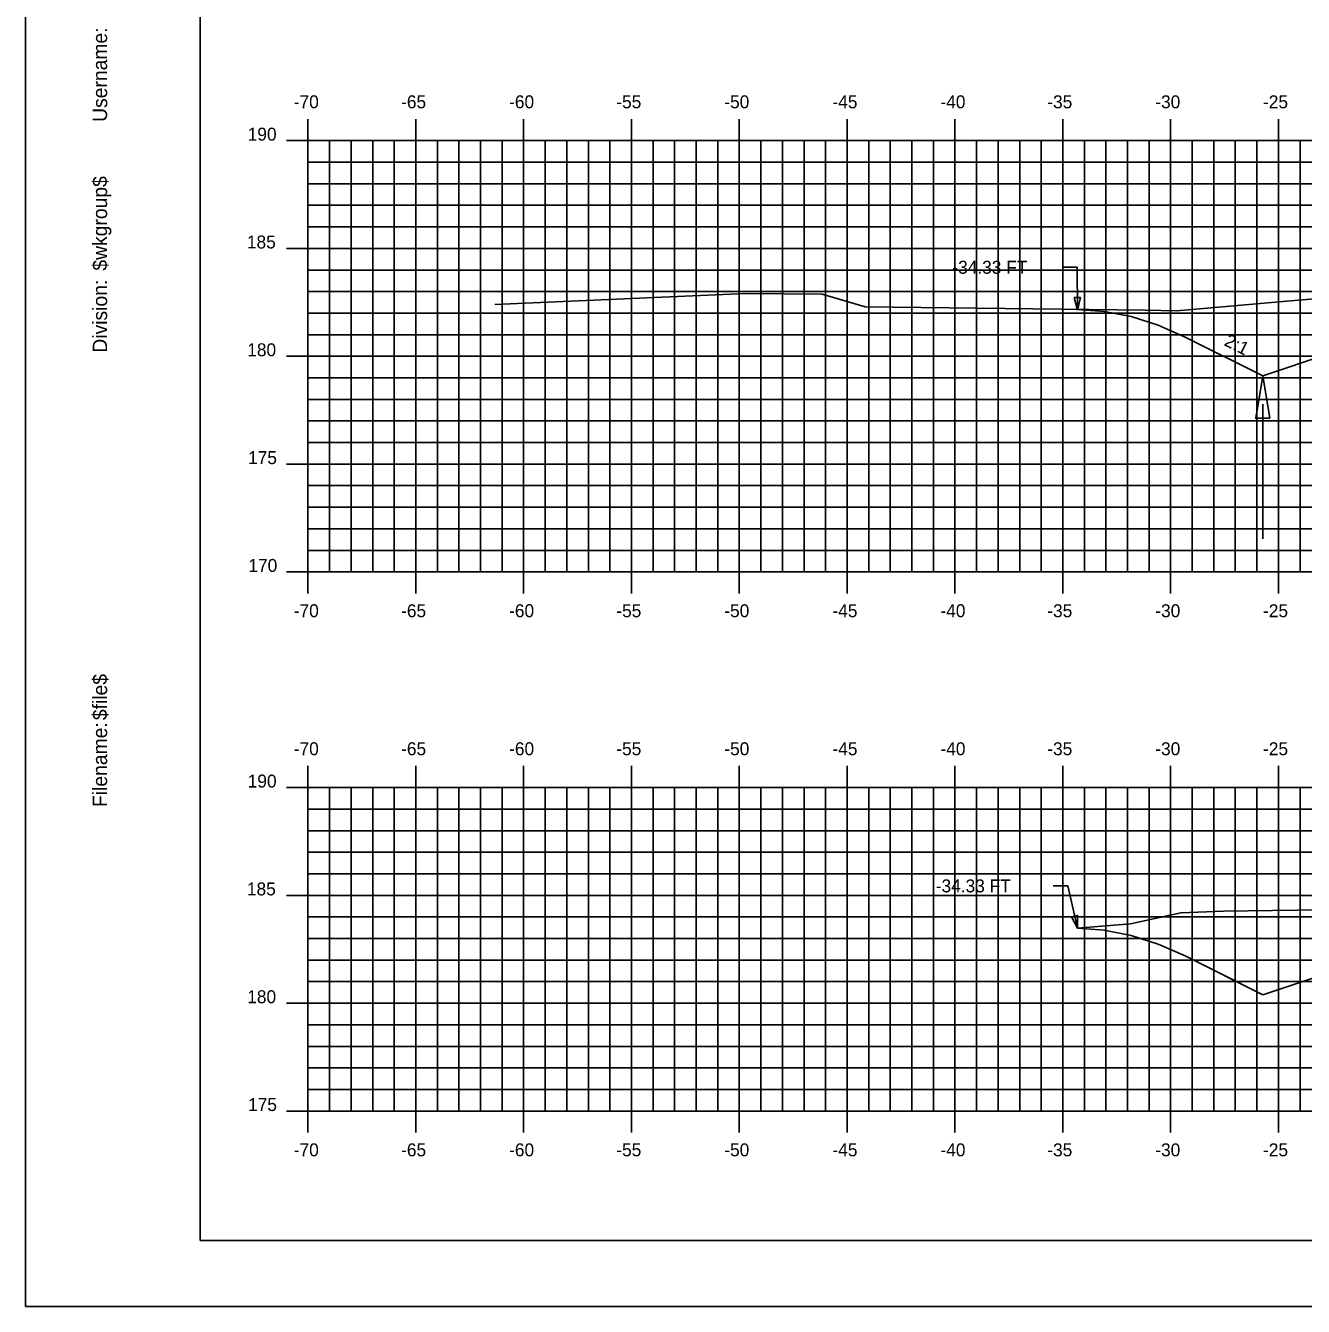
# Model space of a CAD drawing. Extents: x 1139872 to 1140042, y 608981 to 609091.
# Drawn here: x 1139871.9 to 1139931.1, y 608981.3 to 609040.7 of the extents above; entities that cross this region are included whole.
import ezdxf

# ---------------------------------------------------------------- set-up
doc = ezdxf.new("R2010")
doc.units = 0
for name, color, linetype in [('ANNOTATION', 7, 'Continuous'), ('BORDER', 7, 'Continuous'), ('D_Drainage_Ditch_Line', 7, 'Continuous'), ('D_Roadway_SlopeLines', 7, 'Continuous'), ('D_Text_Standard', 7, 'Continuous'), ('H_V ANNOTATION', 7, 'Continuous'), ('MAJOR', 7, 'Continuous'), ('MINOR', 7, 'Continuous'), ('PLOT BOUNDARY', 7, 'Continuous'), ('S_Roadway_Centerline', 7, 'Continuous')]:
    doc.layers.add(name, color=color, linetype=linetype)

msp = doc.modelspace()

# ---------------------------------------------------------------- linework, layer by layer
msp.add_lwpolyline([(1139920.649, 609027.509), (1139921.899, 609027.417), (1139923.149, 609027.173), (1139924.399, 609026.776), (1139925.649, 609026.227), (1139929.25, 609024.427), (1139932.25, 609025.427), (1139939.974, 609028.001), (1139939.975, 609028.001), (1139943.975, 609028.161), (1139954.975, 609028.381), (1139965.975, 609028.161), (1139969.975, 609028.001), (1139977.698, 609025.427), (1139980.698, 609024.427), (1139983.25, 609025.703), (1139984.5, 609026.247), (1139985.75, 609026.628), (1139987, 609026.848), (1139988.25, 609026.905)])
at = {"layer": 'BORDER'}
msp.add_lwpolyline([(1139879.975, 608984.335), (1140039.975, 608984.335), (1140039.975, 609089.335), (1139879.975, 609089.335)], close=True, dxfattribs=at)
at = {"layer": 'D_Drainage_Ditch_Line'}
msp.add_line((1139929.25, 609023.115), (1139929.25, 609016.871), dxfattribs=at)
msp.add_lwpolyline([(1139929.578, 609022.458), (1139928.922, 609022.458), (1139929.25, 609024.427)], close=True, dxfattribs=at)
at = {"layer": 'D_Roadway_SlopeLines'}
msp.add_line((1139929.25, 608995.726), (1139927.25, 608996.726), dxfattribs=at)
for points in [[(1139929.25, 609024.427), (1139925.649, 609026.227), (1139924.399, 609026.776), (1139923.149, 609027.173), (1139921.899, 609027.417), (1139920.649, 609027.509)], [(1139932.25, 609025.427), (1139929.25, 609024.427)], [(1139939.975, 608999.301), (1139929.25, 608995.726)], [(1139929.25, 608995.726), (1139925.649, 608997.527), (1139924.399, 608998.075), (1139923.149, 608998.472), (1139921.899, 608998.716), (1139920.649, 608998.808)]]:
    msp.add_lwpolyline(points, dxfattribs=at)
at = {"layer": 'D_Text_Standard'}
for points in [[(1139920.649, 609027.477), (1139920.645, 609029.461), (1139919.965, 609029.461)], [(1139920.649, 608998.808), (1139920.209, 609000.775), (1139919.529, 609000.775)]]:
    msp.add_lwpolyline(points, dxfattribs=at)
for points in [[(1139920.649, 609027.477), (1139920.502, 609028.059), (1139920.794, 609028.06)], [(1139920.649, 608998.808), (1139920.38, 608999.345), (1139920.664, 608999.408)]]:
    msp.add_lwpolyline(points, close=True, dxfattribs=at)
at = {"layer": 'MAJOR'}
for p, q in [((1139884.975, 609036.337), (1139884.975, 609035.335)), ((1139889.975, 609036.337), (1139889.975, 609035.335)), ((1139894.975, 609036.337), (1139894.975, 609035.335)), ((1139899.975, 609036.337), (1139899.975, 609035.335)), ((1139904.975, 609036.337), (1139904.975, 609035.335)), ((1139909.975, 609036.337), (1139909.975, 609035.335)), ((1139914.975, 609036.337), (1139914.975, 609035.335)), ((1139919.975, 609036.337), (1139919.975, 609035.335)), ((1139924.975, 609036.337), (1139924.975, 609035.335)), ((1139929.975, 609036.337), (1139929.975, 609035.335)), ((1139883.973, 609035.335), (1139884.975, 609035.335)), ((1139884.975, 609035.335), (1140024.975, 609035.335)), ((1139884.975, 609015.335), (1139884.975, 609035.335)), ((1139884.975, 609015.335), (1139884.975, 609035.335)), ((1139884.975, 609035.335), (1140024.975, 609035.335)), ((1139889.975, 609015.335), (1139889.975, 609035.335)), ((1139894.975, 609015.335), (1139894.975, 609035.335)), ((1139899.975, 609015.335), (1139899.975, 609035.335)), ((1139904.975, 609015.335), (1139904.975, 609035.335)), ((1139909.975, 609015.335), (1139909.975, 609035.335)), ((1139914.975, 609015.335), (1139914.975, 609035.335)), ((1139919.975, 609015.335), (1139919.975, 609035.335)), ((1139924.975, 609015.335), (1139924.975, 609035.335)), ((1139929.975, 609015.335), (1139929.975, 609035.335)), ((1139883.973, 609030.335), (1139884.975, 609030.335)), ((1139884.975, 609030.335), (1140024.975, 609030.335)), ((1139883.973, 609025.335), (1139884.975, 609025.335)), ((1139884.975, 609025.335), (1140024.975, 609025.335)), ((1139883.973, 609020.335), (1139884.975, 609020.335)), ((1139884.975, 609020.335), (1140024.975, 609020.335)), ((1139883.973, 609015.335), (1139884.975, 609015.335)), ((1139884.975, 609015.335), (1140024.975, 609015.335)), ((1139884.975, 609015.335), (1140024.975, 609015.335)), ((1139884.975, 609014.333), (1139884.975, 609015.335)), ((1139889.975, 609014.333), (1139889.975, 609015.335)), ((1139894.975, 609014.333), (1139894.975, 609015.335)), ((1139899.975, 609014.333), (1139899.975, 609015.335)), ((1139904.975, 609014.333), (1139904.975, 609015.335)), ((1139909.975, 609014.333), (1139909.975, 609015.335)), ((1139914.975, 609014.333), (1139914.975, 609015.335)), ((1139919.975, 609014.333), (1139919.975, 609015.335)), ((1139924.975, 609014.333), (1139924.975, 609015.335)), ((1139929.975, 609014.333), (1139929.975, 609015.335)), ((1139884.975, 609006.337), (1139884.975, 609005.335)), ((1139889.975, 609006.337), (1139889.975, 609005.335)), ((1139894.975, 609006.337), (1139894.975, 609005.335)), ((1139899.975, 609006.337), (1139899.975, 609005.335)), ((1139904.975, 609006.337), (1139904.975, 609005.335)), ((1139909.975, 609006.337), (1139909.975, 609005.335)), ((1139914.975, 609006.337), (1139914.975, 609005.335)), ((1139919.975, 609006.337), (1139919.975, 609005.335)), ((1139924.975, 609006.337), (1139924.975, 609005.335)), ((1139929.975, 609006.337), (1139929.975, 609005.335)), ((1139883.973, 609005.335), (1139884.975, 609005.335)), ((1139884.975, 609005.335), (1140024.975, 609005.335)), ((1139884.975, 608990.335), (1139884.975, 609005.335)), ((1139884.975, 608990.335), (1139884.975, 609005.335)), ((1139884.975, 609005.335), (1140024.975, 609005.335)), ((1139889.975, 608990.335), (1139889.975, 609005.335)), ((1139894.975, 608990.335), (1139894.975, 609005.335)), ((1139899.975, 608990.335), (1139899.975, 609005.335)), ((1139904.975, 608990.335), (1139904.975, 609005.335)), ((1139909.975, 608990.335), (1139909.975, 609005.335)), ((1139914.975, 608990.335), (1139914.975, 609005.335)), ((1139919.975, 608990.335), (1139919.975, 609005.335)), ((1139924.975, 608990.335), (1139924.975, 609005.335)), ((1139929.975, 608990.335), (1139929.975, 609005.335)), ((1139883.973, 609000.335), (1139884.975, 609000.335)), ((1139884.975, 609000.335), (1140024.975, 609000.335)), ((1139883.973, 608995.335), (1139884.975, 608995.335)), ((1139884.975, 608995.335), (1140024.975, 608995.335)), ((1139883.973, 608990.335), (1139884.975, 608990.335)), ((1139884.975, 608990.335), (1140024.975, 608990.335)), ((1139884.975, 608990.335), (1140024.975, 608990.335)), ((1139884.975, 608989.333), (1139884.975, 608990.335)), ((1139889.975, 608989.333), (1139889.975, 608990.335)), ((1139894.975, 608989.333), (1139894.975, 608990.335)), ((1139899.975, 608989.333), (1139899.975, 608990.335)), ((1139904.975, 608989.333), (1139904.975, 608990.335)), ((1139909.975, 608989.333), (1139909.975, 608990.335)), ((1139914.975, 608989.333), (1139914.975, 608990.335)), ((1139919.975, 608989.333), (1139919.975, 608990.335)), ((1139924.975, 608989.333), (1139924.975, 608990.335)), ((1139929.975, 608989.333), (1139929.975, 608990.335))]:
    msp.add_line(p, q, dxfattribs=at)
at = {"layer": 'MINOR'}
for p, q in [((1139885.975, 609015.335), (1139885.975, 609035.335)), ((1139886.975, 609015.335), (1139886.975, 609035.335)), ((1139887.975, 609015.335), (1139887.975, 609035.335)), ((1139888.975, 609015.335), (1139888.975, 609035.335)), ((1139890.975, 609015.335), (1139890.975, 609035.335)), ((1139891.975, 609015.335), (1139891.975, 609035.335)), ((1139892.975, 609015.335), (1139892.975, 609035.335)), ((1139893.975, 609015.335), (1139893.975, 609035.335)), ((1139895.975, 609015.335), (1139895.975, 609035.335)), ((1139896.975, 609015.335), (1139896.975, 609035.335)), ((1139897.975, 609015.335), (1139897.975, 609035.335)), ((1139898.975, 609015.335), (1139898.975, 609035.335)), ((1139900.975, 609015.335), (1139900.975, 609035.335)), ((1139901.975, 609015.335), (1139901.975, 609035.335)), ((1139902.975, 609015.335), (1139902.975, 609035.335)), ((1139903.975, 609015.335), (1139903.975, 609035.335)), ((1139905.975, 609015.335), (1139905.975, 609035.335)), ((1139906.975, 609015.335), (1139906.975, 609035.335)), ((1139907.975, 609015.335), (1139907.975, 609035.335)), ((1139908.975, 609015.335), (1139908.975, 609035.335)), ((1139910.975, 609015.335), (1139910.975, 609035.335)), ((1139911.975, 609015.335), (1139911.975, 609035.335)), ((1139912.975, 609015.335), (1139912.975, 609035.335)), ((1139913.975, 609015.335), (1139913.975, 609035.335)), ((1139915.975, 609015.335), (1139915.975, 609035.335)), ((1139916.975, 609015.335), (1139916.975, 609035.335)), ((1139917.975, 609015.335), (1139917.975, 609035.335)), ((1139918.975, 609015.335), (1139918.975, 609035.335)), ((1139920.975, 609015.335), (1139920.975, 609035.335)), ((1139921.975, 609015.335), (1139921.975, 609035.335)), ((1139922.975, 609015.335), (1139922.975, 609035.335)), ((1139923.975, 609015.335), (1139923.975, 609035.335)), ((1139925.975, 609015.335), (1139925.975, 609035.335)), ((1139926.975, 609015.335), (1139926.975, 609035.335)), ((1139927.975, 609015.335), (1139927.975, 609035.335)), ((1139928.975, 609015.335), (1139928.975, 609035.335)), ((1139930.975, 609015.335), (1139930.975, 609035.335)), ((1139884.975, 609034.335), (1140024.975, 609034.335)), ((1139884.975, 609034.335), (1139885.977, 609034.335)), ((1139884.975, 609033.335), (1140024.975, 609033.335)), ((1139884.975, 609033.335), (1139885.977, 609033.335)), ((1139884.975, 609032.335), (1140024.975, 609032.335)), ((1139884.975, 609032.335), (1139885.977, 609032.335)), ((1139884.975, 609031.335), (1140024.975, 609031.335)), ((1139884.975, 609031.335), (1139885.977, 609031.335)), ((1139884.975, 609029.335), (1140024.975, 609029.335)), ((1139884.975, 609029.335), (1139885.977, 609029.335)), ((1139884.975, 609028.335), (1140024.975, 609028.335)), ((1139884.975, 609028.335), (1139885.977, 609028.335)), ((1139884.975, 609027.335), (1140024.975, 609027.335)), ((1139884.975, 609027.335), (1139885.977, 609027.335)), ((1139884.975, 609026.335), (1140024.975, 609026.335)), ((1139884.975, 609026.335), (1139885.977, 609026.335)), ((1139884.975, 609024.335), (1140024.975, 609024.335)), ((1139884.975, 609024.335), (1139885.977, 609024.335)), ((1139884.975, 609023.335), (1140024.975, 609023.335)), ((1139884.975, 609023.335), (1139885.977, 609023.335)), ((1139884.975, 609022.335), (1140024.975, 609022.335)), ((1139884.975, 609022.335), (1139885.977, 609022.335)), ((1139884.975, 609021.335), (1140024.975, 609021.335)), ((1139884.975, 609021.335), (1139885.977, 609021.335)), ((1139884.975, 609019.335), (1140024.975, 609019.335)), ((1139884.975, 609019.335), (1139885.977, 609019.335)), ((1139884.975, 609018.335), (1140024.975, 609018.335)), ((1139884.975, 609018.335), (1139885.977, 609018.335)), ((1139884.975, 609017.335), (1140024.975, 609017.335)), ((1139884.975, 609017.335), (1139885.977, 609017.335)), ((1139884.975, 609016.335), (1140024.975, 609016.335)), ((1139884.975, 609016.335), (1139885.977, 609016.335)), ((1139885.975, 608990.335), (1139885.975, 609005.335)), ((1139886.975, 608990.335), (1139886.975, 609005.335)), ((1139887.975, 608990.335), (1139887.975, 609005.335)), ((1139888.975, 608990.335), (1139888.975, 609005.335)), ((1139890.975, 608990.335), (1139890.975, 609005.335)), ((1139891.975, 608990.335), (1139891.975, 609005.335)), ((1139892.975, 608990.335), (1139892.975, 609005.335)), ((1139893.975, 608990.335), (1139893.975, 609005.335)), ((1139895.975, 608990.335), (1139895.975, 609005.335)), ((1139896.975, 608990.335), (1139896.975, 609005.335)), ((1139897.975, 608990.335), (1139897.975, 609005.335)), ((1139898.975, 608990.335), (1139898.975, 609005.335)), ((1139900.975, 608990.335), (1139900.975, 609005.335)), ((1139901.975, 608990.335), (1139901.975, 609005.335)), ((1139902.975, 608990.335), (1139902.975, 609005.335)), ((1139903.975, 608990.335), (1139903.975, 609005.335)), ((1139905.975, 608990.335), (1139905.975, 609005.335)), ((1139906.975, 608990.335), (1139906.975, 609005.335)), ((1139907.975, 608990.335), (1139907.975, 609005.335)), ((1139908.975, 608990.335), (1139908.975, 609005.335)), ((1139910.975, 608990.335), (1139910.975, 609005.335)), ((1139911.975, 608990.335), (1139911.975, 609005.335)), ((1139912.975, 608990.335), (1139912.975, 609005.335)), ((1139913.975, 608990.335), (1139913.975, 609005.335)), ((1139915.975, 608990.335), (1139915.975, 609005.335)), ((1139916.975, 608990.335), (1139916.975, 609005.335)), ((1139917.975, 608990.335), (1139917.975, 609005.335)), ((1139918.975, 608990.335), (1139918.975, 609005.335)), ((1139920.975, 608990.335), (1139920.975, 609005.335)), ((1139921.975, 608990.335), (1139921.975, 609005.335)), ((1139922.975, 608990.335), (1139922.975, 609005.335)), ((1139923.975, 608990.335), (1139923.975, 609005.335)), ((1139925.975, 608990.335), (1139925.975, 609005.335)), ((1139926.975, 608990.335), (1139926.975, 609005.335)), ((1139927.975, 608990.335), (1139927.975, 609005.335)), ((1139928.975, 608990.335), (1139928.975, 609005.335)), ((1139930.975, 608990.335), (1139930.975, 609005.335)), ((1139884.975, 609004.335), (1140024.975, 609004.335)), ((1139884.975, 609004.335), (1139885.977, 609004.335)), ((1139884.975, 609003.335), (1140024.975, 609003.335)), ((1139884.975, 609003.335), (1139885.977, 609003.335)), ((1139884.975, 609002.335), (1140024.975, 609002.335)), ((1139884.975, 609002.335), (1139885.977, 609002.335)), ((1139884.975, 609001.335), (1140024.975, 609001.335)), ((1139884.975, 609001.335), (1139885.977, 609001.335)), ((1139884.975, 608999.335), (1140024.975, 608999.335)), ((1139884.975, 608999.335), (1139885.977, 608999.335)), ((1139884.975, 608998.335), (1140024.975, 608998.335)), ((1139884.975, 608998.335), (1139885.977, 608998.335)), ((1139884.975, 608997.335), (1140024.975, 608997.335)), ((1139884.975, 608997.335), (1139885.977, 608997.335)), ((1139884.975, 608996.335), (1140024.975, 608996.335)), ((1139884.975, 608996.335), (1139885.977, 608996.335)), ((1139884.975, 608994.335), (1140024.975, 608994.335)), ((1139884.975, 608994.335), (1139885.977, 608994.335)), ((1139884.975, 608993.335), (1140024.975, 608993.335)), ((1139884.975, 608993.335), (1139885.977, 608993.335)), ((1139884.975, 608992.335), (1140024.975, 608992.335)), ((1139884.975, 608992.335), (1139885.977, 608992.335)), ((1139884.975, 608991.335), (1140024.975, 608991.335)), ((1139884.975, 608991.335), (1139885.977, 608991.335))]:
    msp.add_line(p, q, dxfattribs=at)
at = {"layer": 'PLOT BOUNDARY'}
msp.add_lwpolyline([(1139871.882, 608981.276), (1140041.882, 608981.276), (1140041.882, 609091.276), (1139871.882, 609091.276)], close=True, dxfattribs=at)
at = {"layer": 'S_Roadway_Centerline'}
for p, q in [((1139925.454, 608999.519), (1139923.111, 608999.009)), ((1139923.111, 608999.009), (1139920.649, 608998.808))]:
    msp.add_line(p, q, dxfattribs=at)
for points in [[(1139893.645, 609027.734), (1139905.275, 609028.246), (1139908.821, 609028.218), (1139910.807, 609027.635), (1139923.798, 609027.469), (1139925.261, 609027.441), (1139930.896, 609027.93), (1139933.431, 609028.135)], [(1139925.454, 608999.519), (1139927.426, 608999.596), (1139935.382, 608999.714), (1139940.06, 608999.683), (1139942.405, 608999.588), (1139945.203, 608999.576), (1139951.394, 608999.616), (1139955.847, 608999.66), (1139957.155, 608999.621), (1139967.256, 608999.38), (1139968.387, 608999.254), (1139969.506, 608999.074), (1139972.265, 608999.073), (1139994.365, 608998.121), (1139997.682, 608998.063), (1140024.975, 608997.611)]]:
    msp.add_lwpolyline(points, dxfattribs=at)

# ---------------------------------------------------------------- texts
at = {"layer": 'ANNOTATION'}
msp.add_text('2:1', height=0.6, rotation=333.43495, dxfattribs=at).set_placement((1139927.417, 609025.862))
at = {"layer": 'BORDER'}
for s, p in [('Username:', (1139875.66, 609036.203)), ('$wkgroup$', (1139875.66, 609029.305)), ('Division:', (1139875.66, 609025.501)), ('$file$', (1139875.66, 609008.461)), ('Filename:', (1139875.66, 609004.433))]:
    msp.add_text(s, height=0.6696, rotation=90, dxfattribs=at).set_placement(p)
at = {"layer": 'D_Text_Standard'}
for p in [(1139914.853, 609029.161), (1139914.085, 609000.475)]:
    msp.add_text('-34.33 FT', height=0.6, dxfattribs=at).set_placement(p)
at = {"layer": 'H_V ANNOTATION'}
for s, p in [('-70', (1139884.316, 609036.835)), ('-65', (1139889.293, 609036.835)), ('-60', (1139894.301, 609036.835)), ('-55', (1139899.271, 609036.835)), ('-50', (1139904.279, 609036.835)), ('-45', (1139909.293, 609036.835)), ('-40', (1139914.301, 609036.835)), ('-35', (1139919.255, 609036.835)), ('-30', (1139924.263, 609036.835)), ('-25', (1139929.26, 609036.835)), ('190', (1139882.18, 609035.335)), ('185', (1139882.142, 609030.335)), ('180', (1139882.158, 609025.335)), ('175', (1139882.196, 609020.335)), ('170', (1139882.212, 609015.335)), ('-70', (1139884.316, 609013.235)), ('-65', (1139889.293, 609013.235)), ('-60', (1139894.301, 609013.235)), ('-55', (1139899.271, 609013.235)), ('-50', (1139904.279, 609013.235)), ('-45', (1139909.293, 609013.235)), ('-40', (1139914.301, 609013.235)), ('-35', (1139919.255, 609013.235)), ('-30', (1139924.263, 609013.235)), ('-25', (1139929.26, 609013.235)), ('-70', (1139884.316, 609006.835)), ('-65', (1139889.293, 609006.835)), ('-60', (1139894.301, 609006.835)), ('-55', (1139899.271, 609006.835)), ('-50', (1139904.279, 609006.835)), ('-45', (1139909.293, 609006.835)), ('-40', (1139914.301, 609006.835)), ('-35', (1139919.255, 609006.835)), ('-30', (1139924.263, 609006.835)), ('-25', (1139929.26, 609006.835)), ('190', (1139882.18, 609005.335)), ('185', (1139882.142, 609000.335)), ('180', (1139882.158, 608995.335)), ('175', (1139882.196, 608990.335)), ('-70', (1139884.316, 608988.235)), ('-65', (1139889.293, 608988.235)), ('-60', (1139894.301, 608988.235)), ('-55', (1139899.271, 608988.235)), ('-50', (1139904.279, 608988.235)), ('-45', (1139909.293, 608988.235)), ('-40', (1139914.301, 608988.235)), ('-35', (1139919.255, 608988.235)), ('-30', (1139924.263, 608988.235)), ('-25', (1139929.26, 608988.235))]:
    msp.add_text(s, height=0.6, dxfattribs=at).set_placement(p)
at = {"layer": 'MAJOR'}
for p in [(1139884.97, 609015.335), (1139884.97, 608990.335)]:
    msp.add_text('-', height=0.006, dxfattribs=at).set_placement(p)

doc.saveas('drawing.dxf')
